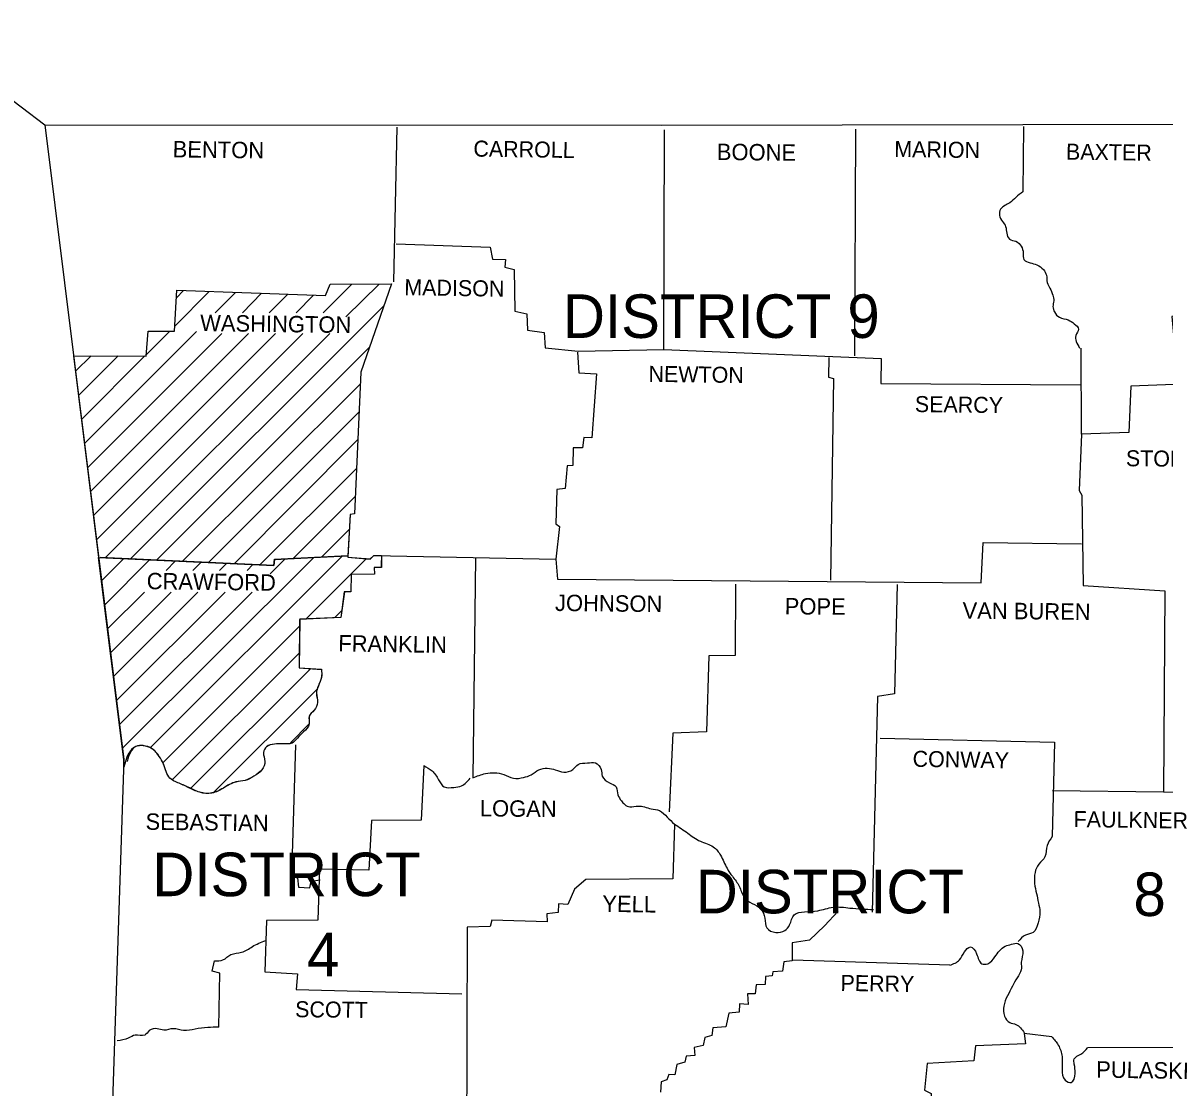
# Model space of a CAD drawing. Extents: x 21307 to 29830, y 1322443 to 1332359.
# Drawn here: x 25199.5 to 25498.6, y 1326251 to 1326529.7 of the extents above; entities that cross this region are included whole.
import ezdxf

# ---------------------------------------------------------------- set-up
doc = ezdxf.new("R2010")
doc.units = 0
doc.layers.add('R_Draft', color=7, linetype='Continuous')
doc.layers.add('R_No Plot', color=7, linetype='Continuous')

msp = doc.modelspace()

# ---------------------------------------------------------------- linework, layer by layer
at = {"layer": 'R_Draft'}
for points in [[(25205.26, 1326503), (25366.96, 1326502.9), (25508.86, 1326503.2), (25676.26, 1326505.8), (25753.86, 1326507.6)], [(25205.26, 1326503), (25225.96, 1326336.8), (25216.96, 1326065.5)], [(25297.56, 1326502.4), (25296.66, 1326461.9)], [(25297.36, 1326471.8), (25321.96, 1326471), (25322.56, 1326467.8), (25325.96, 1326467.7), (25325.86, 1326465.7), (25328.26, 1326465.1), (25328.46, 1326454.2), (25331.56, 1326453.5), (25331.76, 1326449.2), (25336.16, 1326448.6), (25336.36, 1326444.6), (25345.06, 1326443.7), (25367.46, 1326444.2), (25367.66, 1326501.7)], [(25417.76, 1326501.9), (25417.46, 1326442.5)], [(25461.76, 1326502.6), (25461.56, 1326485.5)], [(25508.86, 1326502.6), (25509.06, 1326478.8), (25507.36, 1326478.7), (25507.66, 1326453.8), (25500.66, 1326452.8), (25501.26, 1326446.1), (25503.66, 1326443), (25503.46, 1326435.1), (25489.86, 1326434.6), (25489.36, 1326422.4), (25476.96, 1326422), (25476.36, 1326407.2), (25477.06, 1326406), (25477.36, 1326382.4), (25498.76, 1326381), (25498.46, 1326328.3), (25515.46, 1326327.8), (25515.46, 1326274.2), (25502.06, 1326273.2), (25501.06, 1326261.4), (25478.56, 1326261.3)], [(25213.16, 1326442.5), (25231.86, 1326442.4), (25232.36, 1326449), (25239.26, 1326449), (25239.86, 1326459.7), (25278.86, 1326458.3), (25280.06, 1326461.3), (25296.16, 1326461.4), (25288.06, 1326438.2), (25286.46, 1326401.1), (25285.26, 1326401), (25284.66, 1326389.8), (25290.56, 1326389.3), (25291.46, 1326390.2), (25339.16, 1326389.3), (25339.66, 1326384)], [(25213.16, 1326442.5), (25231.86, 1326442.4), (25232.36, 1326449), (25239.26, 1326449), (25239.86, 1326459.7), (25278.86, 1326458.3), (25280.06, 1326461.3), (25296.16, 1326461.4), (25288.06, 1326438.2), (25286.46, 1326401.1), (25285.26, 1326401), (25284.66, 1326390.1)], [(25239.36, 1326450.3), (25248.36, 1326459.4)], [(25239.76, 1326457.7), (25241.66, 1326459.6)], [(25249.96, 1326453.8), (25255.26, 1326459.1)], [(25257.06, 1326453.8), (25262.06, 1326458.9)], [(25264.06, 1326453.8), (25268.96, 1326458.7)], [(25278.26, 1326453.8), (25285.76, 1326461.3)], [(25284.16, 1326452.7), (25292.86, 1326461.3)], [(25227.86, 1326389.4), (25294.06, 1326455.5)], [(25271.16, 1326453.8), (25275.66, 1326458.4)], [(25215.76, 1326419.6), (25245.06, 1326448.9)], [(25216.56, 1326413.3), (25251.66, 1326448.4)], [(25217.36, 1326407.1), (25258.66, 1326448.4)], [(25218.16, 1326400.8), (25265.76, 1326448.4)], [(25218.96, 1326394.5), (25272.86, 1326448.4)], [(25221.16, 1326389.7), (25279.96, 1326448.4)], [(25231.96, 1326442.9), (25238.06, 1326449)], [(25234.66, 1326389.1), (25290.26, 1326444.7)], [(25367.46, 1326444.2), (25424.46, 1326441.8), (25424.36, 1326435.3), (25476.66, 1326434.9)], [(25476.96, 1326422), (25476.86, 1326444.5)], [(25219.46, 1326389.7), (25212.86, 1326442.5)], [(25213.36, 1326438.5), (25217.46, 1326442.5)], [(25214.16, 1326432.2), (25224.46, 1326442.5)], [(25214.96, 1326425.9), (25231.46, 1326442.5)], [(25344.86, 1326443.5), (25345.26, 1326438.1), (25349.86, 1326437.8), (25348.66, 1326421), (25346.56, 1326421.1), (25346.16, 1326418.4), (25343.76, 1326418.4), (25343.66, 1326413.8), (25342.16, 1326413.7), (25341.66, 1326407.8), (25339.46, 1326407.5), (25339.16, 1326398.5), (25340.16, 1326397.8), (25339.16, 1326389.3)], [(25410.76, 1326442.1), (25410.66, 1326436.9), (25411.96, 1326436.6), (25411.16, 1326383.8)], [(25241.36, 1326388.7), (25287.96, 1326435.2)], [(25248.16, 1326388.4), (25287.56, 1326427.8)], [(25254.96, 1326388.1), (25287.26, 1326420.5)], [(25261.66, 1326387.8), (25286.96, 1326413)], [(25270.36, 1326389.4), (25286.56, 1326405.6)], [(25277.86, 1326389.9), (25285.06, 1326397)], [(25339.66, 1326384), (25450.66, 1326383.1), (25451.16, 1326393.6), (25476.96, 1326393.3)], [(25219.37, 1326389.72), (25265.27, 1326387.62), (25265.47, 1326389.22), (25284.47, 1326390.12)], [(25225.97, 1326334.82), (25225.97, 1326336.82), (25219.37, 1326389.72)], [(25219.76, 1326389.7), (25265.26, 1326387.6), (25265.46, 1326389.2), (25284.46, 1326390.1)], [(25284.66, 1326390.1), (25265.46, 1326389.2), (25265.26, 1326387.6), (25219.76, 1326389.7)], [(25232.97, 1326339.92), (25283.17, 1326390.02)], [(25293.47, 1326390.22), (25293.47, 1326387.12), (25291.57, 1326387.12), (25291.67, 1326385.32), (25285.57, 1326385.22), (25285.47, 1326380.72), (25283.77, 1326380.72), (25282.87, 1326374.02), (25272.07, 1326373.52), (25271.97, 1326360.82), (25277.77, 1326360.42)], [(25284.67, 1326390.12), (25284.67, 1326389.82), (25290.57, 1326389.32), (25291.47, 1326390.22), (25293.47, 1326390.22)], [(25318.16, 1326389.7), (25317.46, 1326332)], [(25220.17, 1326383.62), (25225.97, 1326389.42)], [(25220.97, 1326377.32), (25232.67, 1326389.12)], [(25225.67, 1326339.72), (25275.67, 1326389.62)], [(25237.07, 1326386.32), (25239.47, 1326388.72)], [(25244.07, 1326386.32), (25246.17, 1326388.42)], [(25251.07, 1326386.32), (25252.97, 1326388.22)], [(25258.27, 1326386.32), (25259.77, 1326387.82)], [(25264.37, 1326385.42), (25268.17, 1326389.22)], [(25293.46, 1326388.9), (25293.46, 1326387.1), (25291.56, 1326387.1), (25291.66, 1326385.3), (25285.56, 1326385.2), (25285.46, 1326380.7), (25283.76, 1326380.7), (25282.86, 1326374), (25272.06, 1326373.5), (25271.96, 1326360.8), (25277.76, 1326360.4)], [(25273.77, 1326373.62), (25289.57, 1326389.42)], [(25386.29, 1326382.73), (25386.19, 1326364.03), (25379.29, 1326363.93), (25378.69, 1326344.03), (25369.89, 1326343.73), (25368.89, 1326323.13)], [(25428.64, 1326382.62), (25427.91, 1326354.03), (25423.51, 1326353.29), (25422.05, 1326296.83)], [(25221.77, 1326371.12), (25231.37, 1326380.62)], [(25222.57, 1326364.82), (25238.37, 1326380.62)], [(25223.27, 1326358.52), (25245.37, 1326380.62)], [(25224.07, 1326352.22), (25252.57, 1326380.62)], [(25224.87, 1326345.92), (25259.57, 1326380.62)], [(25281.17, 1326373.92), (25283.07, 1326375.82)], [(25236.27, 1326336.02), (25272.07, 1326371.82)], [(25238.77, 1326331.52), (25272.07, 1326364.82)], [(25243.57, 1326329.32), (25274.97, 1326360.62)], [(25249.57, 1326328.22), (25276.67, 1326355.22)], [(25269.67, 1326341.12), (25274.57, 1326346.12)], [(25424.16, 1326342.4), (25469.86, 1326341.3), (25469.26, 1326316.6)], [(25270.96, 1326340.6), (25269.96, 1326306.2), (25271.46, 1326305.8), (25271.76, 1326303.4), (25274.76, 1326303.2), (25275.06, 1326304.9), (25277.46, 1326305.3)], [(25304.56, 1326335.2), (25303.86, 1326320.9), (25290.86, 1326320.8), (25290.16, 1326307.8), (25277.26, 1326308.1), (25276.86, 1326294.7), (25263.36, 1326294.6), (25262.96, 1326281.2), (25271.46, 1326280.7), (25271.16, 1326276.6), (25314.56, 1326275.4)], [(25469.36, 1326328.7), (25498.46, 1326328.3)], [(25370.26, 1326319.9), (25369.86, 1326305.5), (25347.06, 1326305.4), (25344.06, 1326302.8), (25342.36, 1326298.8), (25339.86, 1326299), (25339.76, 1326296.7), (25336.86, 1326296.4), (25336.96, 1326294.3), (25322.46, 1326294.7), (25321.96, 1326293.1), (25315.96, 1326292.9), (25315.76, 1326234.54)], [(25413.16, 1326297.1), (25409.56, 1326293.2), (25405.66, 1326289.5), (25401.16, 1326288.8), (25401.16, 1326284.1), (25398.96, 1326283.8), (25398.56, 1326281.4), (25396.06, 1326281.2), (25395.86, 1326280.1), (25394.16, 1326280), (25394.06, 1326277.9), (25391.66, 1326277.8), (25391.46, 1326275.4), (25389.46, 1326275.4), (25389.56, 1326272.6), (25387.36, 1326272.8), (25387.26, 1326270.6), (25384.56, 1326270.4), (25383.76, 1326266.8), (25380.36, 1326266.5), (25380.06, 1326264.5), (25378.26, 1326264), (25377.76, 1326261.9), (25375.46, 1326261.4), (25375.66, 1326259.3), (25373.36, 1326259.1), (25372.96, 1326257.5), (25370.86, 1326256.9), (25370.36, 1326254.2), (25368.76, 1326254.3), (25368.26, 1326252.9), (25366.76, 1326252.4), (25366.66, 1326249.7)], [(25250.86, 1326266.7), (25251.16, 1326280.8), (25249.16, 1326281.4), (25249.76, 1326284.1)], [(25442.46, 1326282.9), (25401.26, 1326284.2)], [(25469.16, 1326264.2), (25461.96, 1326265), (25462.26, 1326262.3), (25449.16, 1326261.8), (25448.76, 1326257.9), (25436.46, 1326257.2), (25435.76, 1326250.2), (25437.56, 1326249.3), (25437.56, 1326244.7)]]:
    msp.add_lwpolyline(points, dxfattribs=at)
for points in [[(25461.56, 1326485.5), (25459.76, 1326484), (25458.16, 1326482.6), (25455.76, 1326480.9), (25455.46, 1326479.3), (25456.26, 1326477.7), (25457.06, 1326476.4), (25457.36, 1326474.6), (25458.06, 1326473.1), (25459.76, 1326472.5), (25461.16, 1326471.2), (25461.66, 1326469.4), (25461.86, 1326467.7), (25463.46, 1326466.9), (25465.26, 1326466.3), (25466.96, 1326465.1), (25467.76, 1326463.6), (25467.96, 1326461.7), (25468.66, 1326460.2), (25469.46, 1326458.4), (25469.66, 1326456.9), (25469.46, 1326455.4), (25469.86, 1326454), (25471.16, 1326452.6), (25473.46, 1326451.9), (25475.06, 1326450.9), (25476.16, 1326449.5), (25475.46, 1326447.8), (25475.56, 1326446.3), (25476.46, 1326444.5)], [(25277.77, 1326360.42), (25277.77, 1326358.32), (25276.97, 1326356.12), (25276.47, 1326354.22), (25276.77, 1326351.72), (25275.87, 1326349.72), (25274.57, 1326348.12), (25274.57, 1326346.12), (25273.07, 1326344.02), (25271.47, 1326342.42), (25270.07, 1326341.12), (25267.57, 1326340.92), (25265.47, 1326340.82), (25263.37, 1326340.12), (25262.57, 1326338.62), (25262.97, 1326336.32), (25262.17, 1326334.12), (25260.07, 1326332.42), (25257.77, 1326331.32), (25255.37, 1326330.92), (25252.07, 1326329.32), (25249.07, 1326328.02), (25245.87, 1326328.22), (25242.87, 1326329.52), (25240.17, 1326330.72), (25238.07, 1326331.92), (25236.37, 1326335.62), (25235.27, 1326337.62), (25233.37, 1326339.62), (25231.07, 1326340.42), (25229.17, 1326340.22), (25225.97, 1326334.82)], [(25277.76, 1326360.4), (25277.76, 1326358.3), (25276.96, 1326356.1), (25276.46, 1326354.2), (25276.76, 1326351.7), (25275.86, 1326349.7), (25274.56, 1326348.1), (25274.56, 1326346.1), (25273.06, 1326344), (25271.46, 1326342.4), (25270.06, 1326341.1), (25267.56, 1326340.9), (25265.46, 1326340.8), (25263.36, 1326340.1), (25262.56, 1326338.6), (25262.96, 1326336.3), (25262.16, 1326334.1), (25260.06, 1326332.4), (25257.76, 1326331.3), (25255.36, 1326330.9), (25252.06, 1326329.3), (25249.06, 1326328), (25245.86, 1326328.2), (25242.86, 1326329.5), (25240.16, 1326330.7), (25238.06, 1326331.9), (25236.36, 1326335.6), (25235.26, 1326337.6), (25233.36, 1326339.6), (25231.06, 1326340.4), (25229.16, 1326340.2), (25226.86, 1326336.3)], [(25317.46, 1326332), (25320.76, 1326333.1), (25323.16, 1326333.3), (25325.56, 1326332.9), (25328.06, 1326331.9), (25330.76, 1326332.1), (25332.76, 1326332.8), (25334.76, 1326334.1), (25336.96, 1326334.5), (25339.06, 1326334.1), (25341.26, 1326333.5), (25343.66, 1326334.2), (25345.06, 1326335.5), (25347.46, 1326335.9), (25349.56, 1326335.9), (25351.06, 1326334.2), (25351.36, 1326332.4), (25353.26, 1326330.7), (25354.96, 1326329.6), (25355.46, 1326327.5), (25356.36, 1326326), (25357.26, 1326325), (25358.56, 1326324.4), (25360.76, 1326324.6), (25364.16, 1326323.9), (25366.36, 1326323.4), (25368.36, 1326321.7), (25370.26, 1326319.9)], [(25304.56, 1326335.2), (25306.76, 1326333.8), (25308.46, 1326331.5), (25309.96, 1326329.6), (25312.46, 1326329.5), (25314.46, 1326329.9), (25316.76, 1326331.9)], [(25370.26, 1326319.9), (25373.76, 1326317.5), (25377.06, 1326315.4), (25380.46, 1326313.9), (25382.36, 1326311.7), (25384.06, 1326308.3), (25385.46, 1326306.2), (25387.26, 1326303.6), (25388.56, 1326300.7), (25390.66, 1326299.1), (25392.86, 1326297.7), (25393.96, 1326295.2), (25394.46, 1326292.7), (25396.86, 1326291.5), (25399.16, 1326292), (25400.46, 1326293.5), (25401.66, 1326296.1), (25404.36, 1326296.9), (25407.86, 1326297.2), (25411.86, 1326298.1), (25416.26, 1326297.9), (25422.46, 1326297.5)], [(25469.26, 1326316.6), (25467.96, 1326314.3), (25467.36, 1326311.3), (25465.76, 1326309.4), (25464.76, 1326307.2), (25464.66, 1326304.3), (25465.16, 1326301.7), (25465.66, 1326299.2), (25466.06, 1326296.9), (25465.56, 1326294), (25464.26, 1326291.5), (25462.26, 1326290.8), (25460.36, 1326289.1)], [(25249.76, 1326284.1), (25251.96, 1326284.3), (25254.06, 1326285.7), (25256.86, 1326286.3), (25259.66, 1326287.8), (25263.16, 1326289.4)], [(25442.46, 1326282.9), (25444.96, 1326284.3), (25446.26, 1326286.4), (25447.86, 1326287.7), (25449.46, 1326285.9), (25450.86, 1326283.3), (25452.36, 1326283.3), (25454.26, 1326285.1), (25455.46, 1326286.7), (25456.96, 1326287.9), (25458.56, 1326288.4), (25460.26, 1326288.6), (25461.56, 1326286.7), (25461.16, 1326283.7), (25461.16, 1326281.7), (25460.06, 1326279.6), (25458.86, 1326277.4), (25457.56, 1326274.9), (25456.56, 1326272.2), (25456.76, 1326269.6), (25458.16, 1326267.9), (25459.76, 1326267.4), (25461.96, 1326265.2)], [(25250.86, 1326266.7), (25247.96, 1326266.6), (25244.66, 1326266.2), (25241.66, 1326265.8), (25238.96, 1326266.3), (25236.46, 1326265.9), (25234.76, 1326266.3), (25232.66, 1326265.8), (25231.46, 1326264.6), (25228.96, 1326264.6), (25227.16, 1326263.8), (25224.26, 1326263.1)], [(25469.16, 1326264.2), (25470.86, 1326262), (25471.86, 1326259), (25471.86, 1326255.6), (25472.66, 1326252.8), (25474.26, 1326252.2), (25475.26, 1326254.6), (25475.06, 1326257), (25475.06, 1326258.4), (25476.76, 1326259.6), (25478.56, 1326261.3)]]:
    msp.add_spline(points, degree=3, dxfattribs=at)
at = {"layer": 'R_No Plot'}
msp.add_line((23883.86, 1327502.83), (25205.26, 1326503), dxfattribs=at)

# ---------------------------------------------------------------- texts
at = {"layer": 'R_Draft'}
for s, height, rotation, p in [('BENTON', 4.301, 359.2527, (25238.76, 1326494.5)), ('CARROLL', 4.201, 359.1481, (25317.56, 1326494.7)), ('BOONE', 4.301, 359.4001, (25381.36, 1326493.8)), ('MARION', 4.201, 359.1854, (25427.86, 1326494.6)), ('BAXTER', 4.201, 359.2559, (25472.86, 1326493.9)), ('MADISON', 4.201, 359.0906, (25299.46, 1326458.4)), ('WASHINGTON', 4.3, 359.232, (25245.96, 1326449)), ('NEWTON', 4.201, 359.2717, (25363.46, 1326435.7)), ('SEARCY', 4.199, 359.2527, (25433.26, 1326427.8)), ('STONE', 4.199, 359.4001, (25488.56, 1326413.6)), ('CRAWFORD', 4.299, 359.2771, (25231.96, 1326381.4)), ('JOHNSON', 4.301, 359.3514, (25338.96, 1326375.7)), ('POPE', 4.301, 359.6155, (25399.16, 1326374.8)), ('VAN BUREN', 4.301, 359.3508, (25445.76, 1326373.7)), ('FRANKLIN', 4.301, 359.1815, (25282.16, 1326365.1)), ('CONWAY', 4.199, 359.0371, (25432.66, 1326334.9)), ('LOGAN', 4.301, 359.3969, (25319.26, 1326321.9)), ('SEBASTIAN', 4.299, 359.2816, (25231.66, 1326318.4)), ('FAULKNER', 4.201, 359.2486, (25474.86, 1326319.1)), ('YELL', 4.301, 359.1987, (25351.36, 1326296.9)), ('PERRY', 4.2, 359.0858, (25413.76, 1326276.2)), ('SCOTT', 4.201, 359.4063, (25270.86, 1326269.3)), ('PULASKI', 4.301, 359.053, (25480.76, 1326253.5))]:
    msp.add_text(s, height=height, rotation=rotation, dxfattribs=at).set_placement(p)
for s, p in [('DISTRICT 9', (25341.06, 1326447.2)), ('DISTRICT', (25233.46, 1326301)), ('DISTRICT', (25375.86, 1326296.5)), ('8', (25490.56, 1326295.8)), ('4', (25273.96, 1326280))]:
    msp.add_text(s, height=11.4, dxfattribs=at).set_placement(p)

doc.saveas('drawing.dxf')
